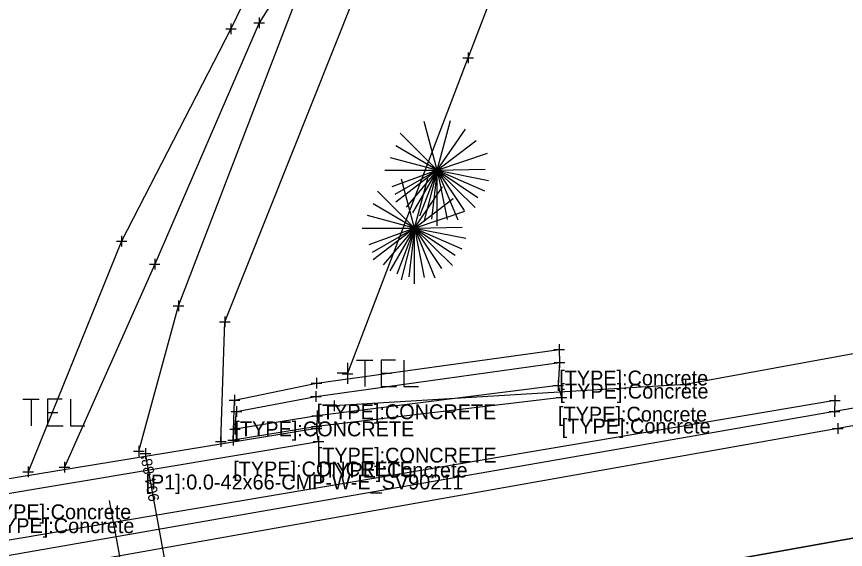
# Model space of a CAD drawing. Extents: x 1386013 to 1389776, y 604170 to 607009.
# Drawn here: x 1388526.5 to 1388604.6, y 605018.1 to 605068.3 of the extents above; entities that cross this region are included whole.
import ezdxf

# ---------------------------------------------------------------- set-up
doc = ezdxf.new("R2010")
doc.units = 0
for name, color, linetype in [('_CIVIL_CONSTRUCTION', 7, 'Continuous'), ('DR_X_Ditch', 7, 'Continuous'), ('DR_X_Headwall', 7, 'Continuous'), ('DR_X_Storm_Sewer', 7, 'Continuous'), ('DR_X_Text', 7, 'Continuous'), ('DV_X_Text', 7, 'Continuous'), ('PM_X_CL_Double_Solid', 7, 'Continuous'), ('PV_X_COP', 7, 'Continuous'), ('PV_X_EOP', 7, 'Continuous'), ('PV_X_Shoulder', 7, 'Continuous'), ('RD_X_Concrete_Pad', 7, 'Continuous'), ('RD_X_GR_Rt', 7, 'Continuous'), ('SC_Scratch1', 7, 'Continuous'), ('SV_X_Break_Lines', 7, 'Continuous'), ('SV_X_Text', 7, 'Continuous'), ('SV_X_Toe_of_Slope', 7, 'Continuous'), ('SV_X_Top_of_Bank', 7, 'Continuous'), ('UT_X_Telecom_Cells', 7, 'Continuous')]:
    doc.layers.add(name, color=color, linetype=linetype)

msp = doc.modelspace()

# ---------------------------------------------------------------- linework, layer by layer
at = {"layer": '_CIVIL_CONSTRUCTION'}
for p, q in [((1388566.103, 605053.853), (1388564.868, 605058.466)), ((1388566.103, 605053.853), (1388567.36, 605058.551)), ((1388566.103, 605053.853), (1388562.613, 605057.34)), ((1388566.103, 605053.853), (1388568.758, 605057.738)), ((1388566.103, 605053.853), (1388569.76, 605056.658)), ((1388566.103, 605053.853), (1388562.196, 605056.15)), ((1388566.103, 605053.853), (1388561.69, 605055.036)), ((1388566.103, 605053.853), (1388570.84, 605055.46)), ((1388561.168, 605053.853), (1388566.103, 605053.853)), ((1388566.103, 605053.853), (1388561.813, 605052.291)), ((1388566.103, 605053.853), (1388562.12, 605051.571)), ((1388566.103, 605053.853), (1388562.196, 605050.858)), ((1388566.103, 605053.853), (1388563.158, 605050.386)), ((1388566.103, 605053.853), (1388563.785, 605049.838)), ((1388566.103, 605053.853), (1388564.438, 605049.513)), ((1388566.103, 605053.853), (1388564.84, 605048.996)), ((1388566.103, 605053.853), (1388565.561, 605049.261)), ((1388566.103, 605053.853), (1388570.613, 605053.945)), ((1388566.103, 605048.613), (1388566.103, 605053.853)), ((1388566.103, 605053.853), (1388567.025, 605049.216)), ((1388566.103, 605053.853), (1388568.036, 605049.185)), ((1388566.103, 605053.853), (1388568.64, 605050.06)), ((1388566.103, 605053.853), (1388569.691, 605050.331)), ((1388566.103, 605053.853), (1388569.925, 605051.298)), ((1388566.103, 605053.853), (1388570.568, 605051.911)), ((1388566.103, 605053.853), (1388570.931, 605052.895)), ((1388563.955, 605048.399), (1388562.72, 605053.012)), ((1388563.955, 605048.399), (1388565.212, 605053.097)), ((1388563.955, 605048.399), (1388560.465, 605051.885)), ((1388563.955, 605048.399), (1388566.61, 605052.284)), ((1388563.955, 605048.399), (1388567.612, 605051.204)), ((1388563.955, 605048.399), (1388560.048, 605050.695)), ((1388563.955, 605048.399), (1388559.542, 605049.582)), ((1388563.955, 605048.399), (1388568.692, 605050.005)), ((1388559.02, 605048.399), (1388563.955, 605048.399)), ((1388563.955, 605048.399), (1388559.665, 605046.837)), ((1388563.955, 605048.399), (1388559.972, 605046.117)), ((1388563.955, 605048.399), (1388560.048, 605045.404)), ((1388563.955, 605048.399), (1388561.01, 605044.932)), ((1388563.955, 605048.399), (1388561.637, 605044.384)), ((1388563.955, 605048.399), (1388562.29, 605044.059)), ((1388563.955, 605048.399), (1388562.692, 605043.542)), ((1388563.955, 605048.399), (1388563.413, 605043.807)), ((1388563.955, 605048.399), (1388568.465, 605048.49)), ((1388563.955, 605043.159), (1388563.955, 605048.399)), ((1388563.955, 605048.399), (1388564.877, 605043.762)), ((1388563.955, 605048.399), (1388565.888, 605043.73)), ((1388563.955, 605048.399), (1388566.492, 605044.605)), ((1388563.955, 605048.399), (1388567.543, 605044.877)), ((1388563.955, 605048.399), (1388567.777, 605045.844)), ((1388563.955, 605048.399), (1388568.42, 605046.457)), ((1388563.955, 605048.399), (1388568.783, 605047.44))]:
    msp.add_line(p, q, dxfattribs=at)
at = {"layer": 'DR_X_Ditch'}
msp.add_lwpolyline([(1388537.976, 605027.368), (1388541.714, 605041.082), (1388552.631, 605069.45), (1388576.076, 605099.211), (1388574.459, 605121.698), (1388591.593, 605151.625)], dxfattribs=at)
at = {"layer": 'DR_X_Headwall'}
msp.add_lwpolyline([(1388523.217, 605024.358), (1388523.509, 605023.049), (1388554.915, 605028.293), (1388554.722, 605029.521)], close=True, dxfattribs=at)
at = {"layer": 'DR_X_Storm_Sewer'}
msp.add_line((1388545.603, 604988.805), (1388538.598, 605027.167), dxfattribs=at)
at = {"layer": 'DR_X_Text'}
msp.add_line((1388535.192, 605022.716), (1388540.125, 604995.7), dxfattribs=at)
at = {"layer": 'DV_X_Text'}
for p, q in [((1388549.315, 605068.261), (1388549.315, 605067.261)), ((1388546.663, 605067.693), (1388546.663, 605066.693)), ((1388548.815, 605067.761), (1388549.815, 605067.761)), ((1388549.315, 605067.761), (1388549.315, 605067.761)), ((1388546.163, 605067.193), (1388547.163, 605067.193)), ((1388546.663, 605067.193), (1388546.663, 605067.193)), ((1388568.514, 605064.45), (1388569.514, 605064.45)), ((1388569.014, 605064.95), (1388569.014, 605063.95)), ((1388569.014, 605064.45), (1388569.014, 605064.45)), ((1388535.856, 605047.184), (1388536.856, 605047.184)), ((1388536.356, 605047.684), (1388536.356, 605046.684)), ((1388536.356, 605047.184), (1388536.356, 605047.184)), ((1388538.97, 605045.013), (1388539.97, 605045.013)), ((1388539.47, 605045.513), (1388539.47, 605044.513)), ((1388539.47, 605045.013), (1388539.47, 605045.013)), ((1388541.214, 605041.082), (1388542.214, 605041.082)), ((1388541.714, 605041.582), (1388541.714, 605040.582)), ((1388541.714, 605041.082), (1388541.714, 605041.082)), ((1388545.585, 605039.563), (1388546.585, 605039.563)), ((1388546.085, 605040.063), (1388546.085, 605039.063)), ((1388546.085, 605039.563), (1388546.085, 605039.563)), ((1388577.092, 605036.972), (1388578.092, 605036.972)), ((1388577.592, 605037.472), (1388577.592, 605036.472)), ((1388577.592, 605036.972), (1388577.592, 605036.972)), ((1388577.62, 605036.232), (1388577.62, 605035.232)), ((1388577.62, 605036.232), (1388577.62, 605035.232)), ((1388577.12, 605035.732), (1388578.12, 605035.732)), ((1388577.12, 605035.732), (1388578.12, 605035.732)), ((1388577.62, 605035.732), (1388577.62, 605035.732)), ((1388577.62, 605035.732), (1388577.62, 605035.732)), ((1388557.139, 605034.678), (1388558.139, 605034.678)), ((1388557.639, 605035.178), (1388557.639, 605034.178)), ((1388557.639, 605034.678), (1388557.639, 605034.678)), ((1388554.716, 605034.291), (1388554.716, 605033.291)), ((1388577.489, 605034.063), (1388577.489, 605033.063)), ((1388577.489, 605034.063), (1388577.489, 605033.063)), ((1388589.514, 605034.156), (1388589.514, 605033.156)), ((1388554.216, 605033.791), (1388555.216, 605033.791)), ((1388554.716, 605033.791), (1388554.716, 605033.791)), ((1388576.989, 605033.563), (1388577.989, 605033.563)), ((1388576.989, 605033.563), (1388577.989, 605033.563)), ((1388577.489, 605033.563), (1388577.489, 605033.563)), ((1388577.489, 605033.563), (1388577.489, 605033.563)), ((1388589.014, 605033.656), (1388590.014, 605033.656)), ((1388589.514, 605033.656), (1388589.514, 605033.656)), ((1388546.985, 605032.674), (1388546.985, 605031.674)), ((1388554.152, 605032.533), (1388555.152, 605032.533)), ((1388554.652, 605033.033), (1388554.652, 605032.033)), ((1388554.652, 605032.533), (1388554.652, 605032.533)), ((1388577.325, 605032.437), (1388578.325, 605032.437)), ((1388577.825, 605032.937), (1388577.825, 605031.937)), ((1388577.825, 605032.437), (1388577.825, 605032.437)), ((1388603.574, 605032.657), (1388603.574, 605031.657)), ((1388546.485, 605032.174), (1388547.485, 605032.174)), ((1388546.985, 605032.174), (1388546.985, 605032.174)), ((1388547.172, 605031.604), (1388547.172, 605030.604)), ((1388555.885, 605031.637), (1388556.885, 605031.637)), ((1388556.385, 605032.137), (1388556.385, 605031.137)), ((1388556.385, 605031.637), (1388556.385, 605031.637)), ((1388603.074, 605032.157), (1388604.074, 605032.157)), ((1388603.544, 605031.623), (1388603.544, 605030.623)), ((1388603.574, 605032.157), (1388603.574, 605032.157)), ((1388546.672, 605031.104), (1388547.672, 605031.104)), ((1388547.172, 605031.104), (1388547.172, 605031.104)), ((1388554.277, 605030.716), (1388555.277, 605030.716)), ((1388554.777, 605031.216), (1388554.777, 605030.216)), ((1388554.777, 605030.716), (1388554.777, 605030.716)), ((1388603.044, 605031.123), (1388604.044, 605031.123)), ((1388603.544, 605031.123), (1388603.544, 605031.123)), ((1388547.038, 605029.956), (1388547.038, 605028.956)), ((1388554.722, 605030.021), (1388554.722, 605029.021)), ((1388554.74, 605030.199), (1388554.74, 605029.199)), ((1388603.872, 605030.022), (1388603.872, 605029.022)), ((1388546.538, 605029.456), (1388547.538, 605029.456)), ((1388547.038, 605029.456), (1388547.038, 605029.456)), ((1388554.222, 605029.521), (1388555.222, 605029.521)), ((1388554.24, 605029.699), (1388555.24, 605029.699)), ((1388554.722, 605029.521), (1388554.722, 605029.521)), ((1388554.74, 605029.699), (1388554.74, 605029.699)), ((1388603.372, 605029.522), (1388604.372, 605029.522)), ((1388603.872, 605029.522), (1388603.872, 605029.522)), ((1388545.709, 605028.796), (1388545.709, 605027.796)), ((1388546.367, 605028.398), (1388547.367, 605028.398)), ((1388546.867, 605028.898), (1388546.867, 605027.898)), ((1388546.867, 605028.398), (1388546.867, 605028.398)), ((1388554.915, 605028.793), (1388554.915, 605027.793)), ((1388537.976, 605027.868), (1388537.976, 605026.868)), ((1388538.598, 605027.667), (1388538.598, 605026.667)), ((1388545.209, 605028.296), (1388546.209, 605028.296)), ((1388545.709, 605028.296), (1388545.709, 605028.296)), ((1388554.415, 605028.293), (1388555.415, 605028.293)), ((1388554.915, 605028.293), (1388554.915, 605028.293)), ((1388537.476, 605027.368), (1388538.476, 605027.368)), ((1388537.976, 605027.368), (1388537.976, 605027.368)), ((1388538.098, 605027.167), (1388539.098, 605027.167)), ((1388538.598, 605027.167), (1388538.598, 605027.167)), ((1388530.964, 605026.378), (1388530.964, 605025.378)), ((1388527.037, 605025.433), (1388528.037, 605025.433)), ((1388527.537, 605025.933), (1388527.537, 605024.933)), ((1388527.537, 605025.433), (1388527.537, 605025.433)), ((1388530.464, 605025.878), (1388531.464, 605025.878)), ((1388530.964, 605025.878), (1388530.964, 605025.878))]:
    msp.add_line(p, q, dxfattribs=at)
at = {"layer": 'PM_X_CL_Double_Solid'}
msp.add_lwpolyline([(1387998.852, 604914.969), (1388072.268, 604927.437), (1388150.341, 604940.542), (1388219.828, 604952.561), (1388327.209, 604971.051), (1388378.925, 604979.712), (1388451.752, 604991.987), (1388527.187, 605005.201), (1388605.277, 605019.172), (1388650.042, 605026.963), (1388727.22, 605040.353), (1388785.545, 605050.583), (1388850.552, 605062.12), (1388924.492, 605075.022), (1388990.903, 605086.799), (1389068.675, 605100.876), (1389141.896, 605114.3), (1389207.534, 605126.394), (1389280.368, 605139.486)], dxfattribs=at)
at = {"layer": 'PV_X_COP'}
msp.add_lwpolyline([(1389280.368, 605139.486), (1389207.534, 605126.394), (1389141.896, 605114.3), (1389068.675, 605100.876), (1388990.903, 605086.799), (1388924.492, 605075.022), (1388850.552, 605062.12), (1388785.545, 605050.583), (1388727.22, 605040.353), (1388650.042, 605026.963), (1388605.277, 605019.172), (1388527.187, 605005.201), (1388451.752, 604991.987), (1388378.925, 604979.712), (1388327.209, 604971.051), (1388219.828, 604952.561), (1388150.341, 604940.542), (1388072.268, 604927.437), (1387998.852, 604914.969)], dxfattribs=at)
at = {"layer": 'PV_X_EOP'}
msp.add_lwpolyline([(1389278.608, 605149.893), (1389205.624, 605136.539), (1389139.992, 605124.612), (1389067.035, 605111.385), (1388989.39, 605097.254), (1388922.829, 605085.432), (1388849.856, 605072.554), (1388784.246, 605061.078), (1388726.082, 605050.998), (1388647.729, 605037.352), (1388603.872, 605029.522), (1388525.264, 605015.568), (1388450.623, 605002.623), (1388377.287, 604990.075), (1388325.535, 604981.408), (1388218.944, 604963.013), (1388149.684, 604951.266), (1388070.904, 604937.92), (1387997.667, 604925.455)], dxfattribs=at)
at = {"layer": 'PV_X_Shoulder'}
msp.add_lwpolyline([(1389278.317, 605151.375), (1389205.256, 605138.274), (1389139.516, 605126.2), (1389066.772, 605113.201), (1388989.159, 605098.99), (1388922.81, 605087.133), (1388849.396, 605074.384), (1388802.288, 605066.592), (1388793.594, 605066.344), (1388786.161, 605070.011), (1388734.228, 605060.313), (1388725.783, 605053.304), (1388647.708, 605038.745), (1388603.544, 605031.123), (1388524.83, 605017.377), (1388449.884, 605004.12), (1388377.375, 604991.893), (1388326.153, 604983.278), (1388218.459, 604964.952), (1388149.618, 604953.156), (1388070.878, 604939.746), (1387997.08, 604927.243)], dxfattribs=at)
at = {"layer": 'RD_X_Concrete_Pad'}
msp.add_lwpolyline([(1388577.592, 605036.972), (1388577.62, 605035.732), (1388577.489, 605033.563), (1388577.825, 605032.437), (1388554.74, 605029.699), (1388546.867, 605028.398), (1388546.985, 605032.174), (1388554.716, 605033.791)], close=True, dxfattribs=at)
at = {"layer": 'RD_X_GR_Rt'}
msp.add_lwpolyline([(1388603.574, 605032.157), (1388524.808, 605018.824), (1388482.129, 605010.885)], dxfattribs=at)
at = {"layer": 'SV_X_Break_Lines'}
msp.add_lwpolyline([(1388577.62, 605035.732), (1388577.489, 605033.563), (1388554.777, 605030.716), (1388547.038, 605029.456), (1388547.172, 605031.104), (1388554.652, 605032.533)], close=True, dxfattribs=at)
at = {"layer": 'SV_X_Toe_of_Slope'}
for points in [[(1388589.438, 605153.522), (1388571.952, 605125.956), (1388573.68, 605106.307), (1388549.315, 605067.761), (1388539.47, 605045.013), (1388530.964, 605025.878)], [(1388545.709, 605028.296), (1388546.085, 605039.563), (1388558.342, 605070.32), (1388577.586, 605097.604), (1388575.492, 605121.742), (1388592.928, 605150.457)], [(1388719.031, 605058.035), (1388646.55, 605044.089), (1388589.514, 605033.656), (1388556.385, 605031.637)]]:
    msp.add_lwpolyline(points, dxfattribs=at)
at = {"layer": 'SV_X_Top_of_Bank'}
for points in [[(1388585.215, 605155.826), (1388569.196, 605126.911), (1388565.442, 605105.903), (1388546.663, 605067.193), (1388536.356, 605047.184), (1388527.537, 605025.433)], [(1388557.639, 605034.678), (1388569.014, 605064.45), (1388581.498, 605096.944), (1388587.228, 605120.725), (1388598.779, 605146.849)]]:
    msp.add_lwpolyline(points, dxfattribs=at)
at = {"layer": 'UT_X_Telecom_Cells'}
for p, q in [((1388557.661, 605033.715), (1388557.661, 605035.715)), ((1388557.661, 605034.715), (1388556.666, 605034.715))]:
    msp.add_line(p, q, dxfattribs=at)
for points in [[(1388558.477, 605035.957), (1388560.033, 605035.957)], [(1388559.265, 605035.957), (1388559.265, 605033.457)], [(1388562.178, 605035.957), (1388560.82, 605035.957), (1388560.82, 605033.457), (1388562.276, 605033.457)], [(1388562.965, 605035.957), (1388562.965, 605033.457), (1388564.323, 605033.457)], [(1388560.82, 605034.716), (1388561.784, 605034.716)], [(1388527.035, 605032.27), (1388528.591, 605032.27)], [(1388527.823, 605032.27), (1388527.823, 605029.77)], [(1388530.736, 605032.27), (1388529.378, 605032.27), (1388529.378, 605029.77), (1388530.834, 605029.77)], [(1388531.523, 605032.27), (1388531.523, 605029.77), (1388532.881, 605029.77)], [(1388529.378, 605031.029), (1388530.342, 605031.029)]]:
    msp.add_lwpolyline(points, dxfattribs=at)

# ---------------------------------------------------------------- texts
at = {"layer": 'SC_Scratch1'}
msp.add_text("904.88'", height=1, rotation=100.34775, dxfattribs=at).set_placement((1388539.916, 605022.733))
at = {"layer": 'SV_X_Text'}
for s, p in [('[TYPE]:Concrete', (1388577.592, 605033.572)), ('[TYPE]:Concrete', (1388577.62, 605032.332)), ('[TYPE]:CONCRETE', (1388554.716, 605030.391)), ('[TYPE]:Concrete', (1388577.489, 605030.163)), ('[TYPE]:CONCRETE', (1388546.985, 605028.774)), ('[TYPE]:Concrete', (1388577.825, 605029.037)), ('[TYPE]:CONCRETE', (1388554.74, 605026.299)), ('[TYPE]:CONCRETE', (1388546.867, 605024.998)), ('[TYPE]:Concrete', (1388554.915, 605024.893)), ('[P1]:0.0-42x66-CMP-W-E_SV90211', (1388538.598, 605023.767)), ('[TYPE]:Concrete', (1388523.217, 605020.958)), ('[TYPE]:Concrete', (1388523.509, 605019.649))]:
    msp.add_text(s, height=1.4, dxfattribs=at).set_placement(p)

doc.saveas('drawing.dxf')
